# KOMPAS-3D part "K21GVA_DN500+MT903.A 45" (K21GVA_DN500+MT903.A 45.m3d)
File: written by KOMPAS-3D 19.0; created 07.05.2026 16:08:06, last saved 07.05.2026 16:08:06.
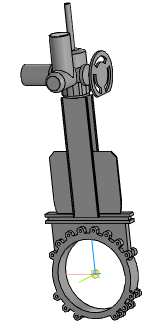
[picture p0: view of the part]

Document properties: Автор: Энергия; Полное имя файла: ..\K21GVA_DN50-DN1000+MT903.A\K21GVA_DN500+MT903.A 45.a3d

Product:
- Part/product: K21GVA_DN500+MT903.A 45
    Масса: 310.847

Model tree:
1. Операция без истории:1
